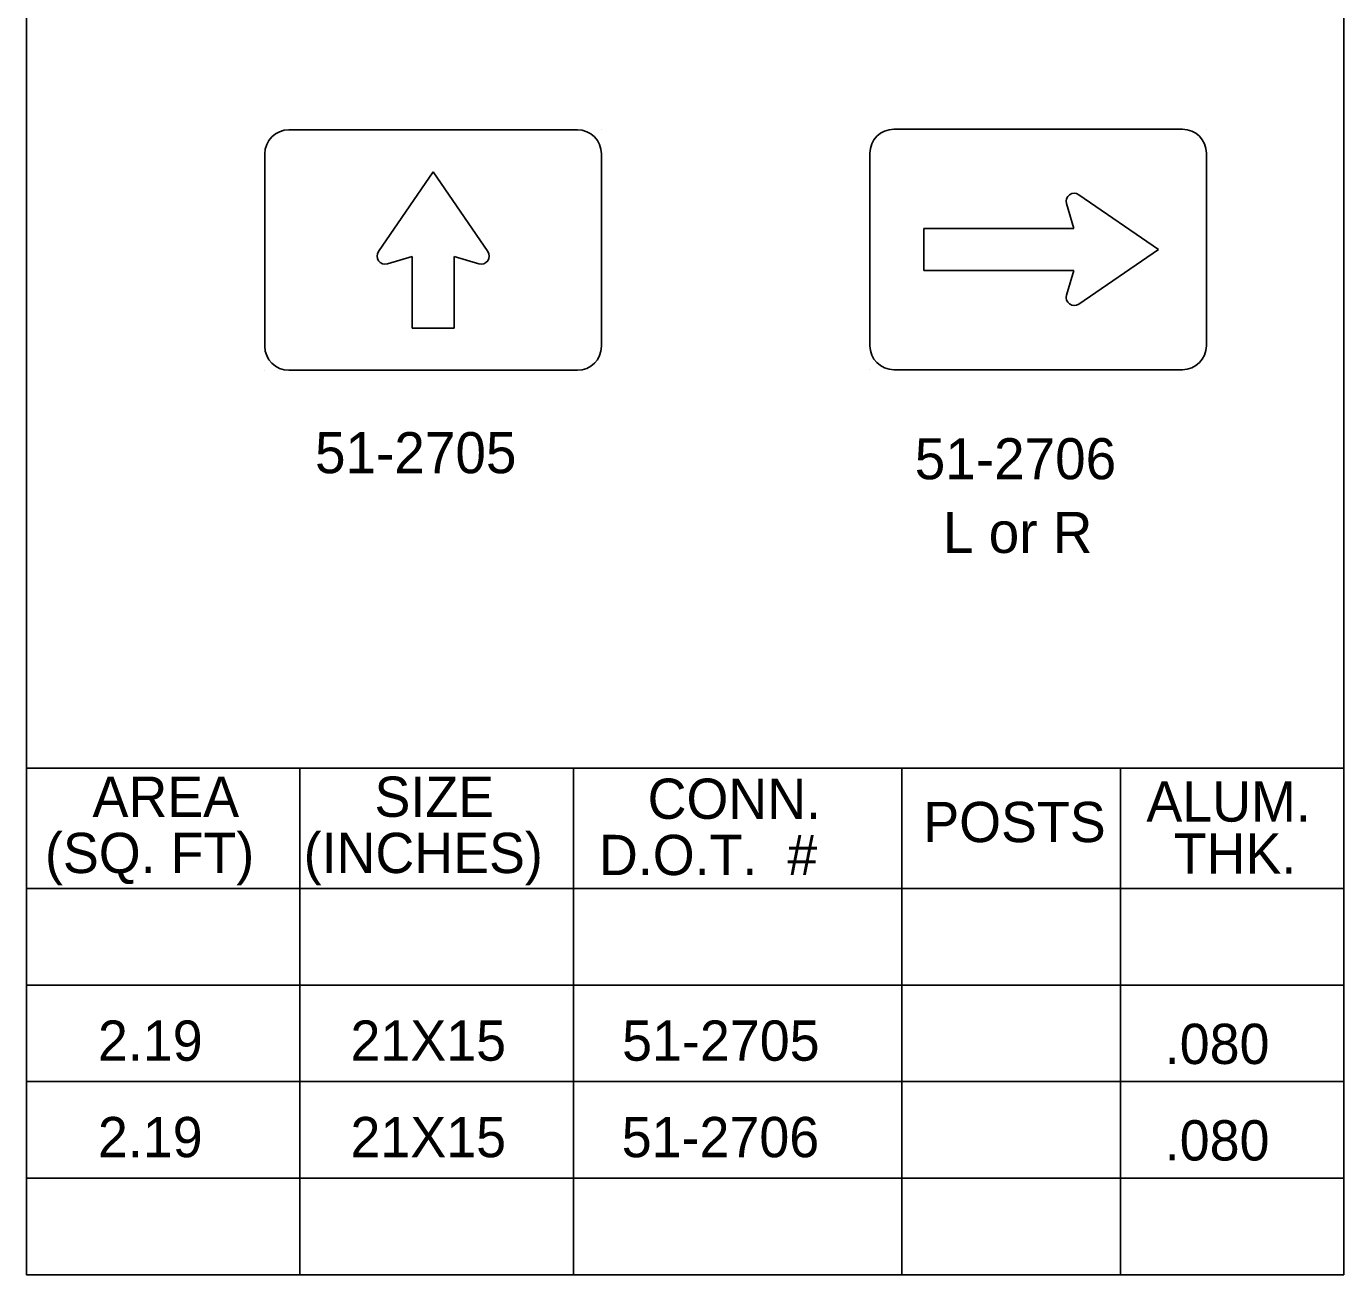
# Model space of a CAD drawing. Extents: x 0 to 2011, y -71 to 1183.
# Drawn here: x 843 to 947.8, y 496.8 to 596.1 of the extents above; entities that cross this region are included whole.
import ezdxf

# ---------------------------------------------------------------- set-up
doc = ezdxf.new("R2010")
doc.units = 0
for name, color, linetype in [('Level 1', 7, 'Continuous'), ('Level 2', 7, 'Continuous'), ('Level 5', 7, 'Continuous')]:
    doc.layers.add(name, color=color, linetype=linetype)

msp = doc.modelspace()

# ---------------------------------------------------------------- linework, layer by layer
at = {"layer": 'Level 1'}
for p, q in [((886.86, 587.83), (863.91, 587.83)), ((934.96, 587.88), (912.02, 587.88)), ((862, 585.92), (862, 570.62)), ((888.77, 570.62), (888.77, 585.92)), ((910.11, 585.97), (910.11, 570.67)), ((936.88, 570.67), (936.88, 585.97)), ((871.04, 578.15), (875.39, 584.48)), ((875.39, 584.48), (875.39, 584.48)), ((875.39, 584.48), (875.39, 584.48)), ((875.39, 584.48), (879.74, 578.15)), ((933.05, 578.32), (926.72, 582.67)), ((925.75, 581.96), (926.34, 579.99)), ((926.34, 579.99), (914.41, 579.99)), ((914.41, 579.99), (914.41, 576.65)), ((926.72, 573.97), (933.05, 578.32)), ((933.05, 578.32), (933.05, 578.32)), ((933.05, 578.32), (933.05, 578.32)), ((873.72, 577.77), (871.75, 577.18)), ((873.72, 572.05), (873.72, 577.77)), ((879.03, 577.18), (877.06, 577.77)), ((877.06, 577.77), (877.06, 572.05)), ((914.41, 576.65), (926.34, 576.65)), ((926.34, 576.65), (925.75, 574.68)), ((877.06, 572.05), (873.72, 572.05)), ((863.91, 568.71), (886.86, 568.71)), ((912.02, 568.76), (934.96, 568.76))]:
    msp.add_line(p, q, dxfattribs=at)
for centre, radius, start, end in [((863.91, 585.92), 1.91, 90, 180), ((886.86, 585.92), 1.91, 0, 90), ((912.02, 585.97), 1.91, 90, 180), ((934.96, 585.97), 1.91, 0, 90), ((926.36, 582.15), 0.637, 55.5114, 196.6409), ((871.56, 577.79), 0.637, 145.5114, 286.6409), ((879.21, 577.79), 0.637, 253.3591, 34.4886), ((926.36, 574.5), 0.637, 163.3591, 304.4886), ((863.91, 570.62), 1.91, 180, 270), ((886.86, 570.62), 1.91, 270, 360), ((912.02, 570.67), 1.91, 180, 270), ((934.96, 570.67), 1.91, 270, 360)]:
    msp.add_arc(centre, radius, start, end, dxfattribs=at)
at = {"layer": 'Level 2'}
for p, q in [((888.77, 587.83), (888.77, 587.83)), ((936.88, 587.88), (936.88, 587.88)), ((875.39, 572.05), (875.39, 572.05)), ((862, 568.71), (862, 568.71)), ((910.11, 568.76), (910.11, 568.76)), ((843.04, 537.09), (947.79, 537.09)), ((864.79, 537.09), (864.79, 496.81)), ((886.54, 537.09), (886.54, 496.81)), ((912.64, 537.09), (912.64, 496.81)), ((930.04, 537.09), (930.04, 496.81)), ((843.04, 527.5), (947.79, 527.5)), ((843.04, 519.83), (947.79, 519.83)), ((843.04, 512.16), (947.79, 512.16)), ((843.04, 504.48), (947.79, 504.48))]:
    msp.add_line(p, q, dxfattribs=at)
msp.add_lwpolyline([(947.79, 600.44), (843.04, 600.44), (843.04, 496.81), (947.79, 496.81)], close=True, dxfattribs=at)
msp.add_lwpolyline([(877.02, 572.05), (877.06, 572.09)], dxfattribs=at)
at = {"layer": 'Level 5'}
for p, q in [((843.04, 830), (843.04, 496.81)), ((947.79, 830), (947.79, 496.81))]:
    msp.add_line(p, q, dxfattribs=at)

# ---------------------------------------------------------------- texts
at = {"layer": 'Level 2'}
for s, height, p in [('51-2705', 3.264, (865.99, 560.53)), ('51-2706', 3.264, (913.68, 560.05)), ('L or R', 3.264, (915.92, 554.19)), ('AREA', 3.2, (848.3, 533.21)), ('SIZE', 3.2, (870.72, 533.21)), ('CONN.', 3.2, (892.44, 533.05)), ('ALUM.', 3.2, (932.1, 532.83)), ('POSTS', 3.2, (914.36, 531.2)), ('(SQ. FT)', 3.2, (844.52, 528.74)), ('(INCHES)', 3.2, (865.09, 528.74)), ('D.O.T.  #', 3.2, (888.57, 528.58)), ('THK.', 3.2, (934.28, 528.69))]:
    msp.add_text(s, height=height, dxfattribs=at).set_placement(p)
at = {"layer": 'Level 5'}
for s, p in [(' 2.19', (847.54, 513.82)), ('21X15', (868.81, 513.82)), ('51-2705', (890.41, 513.82)), ('.080', (933.56, 513.56)), (' 2.19', (847.54, 506.15)), ('21X15', (868.81, 506.15)), ('51-2706', (890.38, 506.15)), ('.080', (933.56, 505.89))]:
    msp.add_text(s, height=3.2, dxfattribs=at).set_placement(p)

doc.saveas('drawing.dxf')
